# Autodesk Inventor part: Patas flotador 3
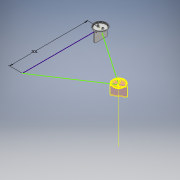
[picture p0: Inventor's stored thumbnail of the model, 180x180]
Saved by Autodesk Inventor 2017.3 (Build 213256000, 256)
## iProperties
Part Number: Patas flotador 3
Material: Genérico
Document SubType Name: Modeling
Designer: PABLO HERNANDEZ
Density: 1 g/cm^3
Appearance: Valor por defecto
Author: PABLO HERNANDEZ
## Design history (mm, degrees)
node "Geometría reparada1"
sketch "Boceto1"
  geometry: C1 r 16 at (0, 0); 1 further point
  constraints: 1 centre point, 1 coincident
  dimensions: "d0" = 32 diameter of C1
extrude "Extrusión1" new body sketch "Boceto1" distance "d1" = 1; taper "d2" = 0 deg; dims "d93" = 1, "d94" = 0
sketch "Boceto2"
  geometry: C1 r 16 at (0, 0); C2 r 15 at (0, 0); C3 r 14 at (0, 0); 1 further point
  constraints: 3 centre point, 1 coincident
  dimensions: "d3" = 1 radial gap between concentric circles of C1 C2; "d4" = 1 radial gap between concentric circles of C2 C3
extrude "Extrusión2" join sketch "Boceto2" distance "d5" = 3; taper "d6" = 0 deg
sketch "Boceto3"
  geometry: C1 r 15 at (0, 0); C2 r 14 at (0, 0); 1 further point
  constraints: 2 centre point, 1 coincident
  dimensions: "d7" = 1 radial gap between concentric circles of C1 C2; "d123" = 30 diameter of C1
extrude "Extrusión3" join sketch "Boceto3" distance "d8" = 2; taper "d9" = 0 deg
sketch "Boceto4"
  geometry: C1 r 16 at (0, 0); 1 further point
  constraints: 1 centre point, 1 coincident
extrude "Extrusión4" cut sketch "Boceto4" distance "d10" = 0.5; taper "d11" = 0 deg
sketch "Boceto7"
  geometry: L1 (1.5, -15.93)-(1.5, 15.93); L2 (-1.5, -15.93)-(-1.5, 15.93); A1 r 16 centre (0, 0) between (1.5, 15.93) and (-1.5, 15.93); A2 r 16 centre (0, 0) between (-1.5, -15.93) and (1.5, -15.93); 2 further points
  constraints: 4 end point, 4 point on circle, 2 centre point, 1 coincident
extrude "Extrusión7" join sketch "Boceto7" distance "d63" = 25; taper "d64" = 0 deg
fillet "Empalme1" dims "d71" = 2
fillet "Empalme2" dims "d95" = 3
fillet "Empalme3" dims "d96" = 0.5
sketch "Boceto12"
  geometry: C1 r 1.2 at (-6, 0); C2 r 1.2 at (6, 0); 2 further points
  constraints: 2 centre point, 1 coincident
  dimensions: "d104" = 6 distance of point (0, 0) point (-6, 0); "d114" = 2.4 diameter of C1; "d115" = 2.4 diameter of C2
extrude "Extrusión9" cut sketch "Boceto12" stored distance "d116" = 10; taper "d117" = 0 deg
sketch "Boceto13"
  geometry: C1 r 1.2 at (-6, 0) reference; C2 r 1.75 at (-6, 0); C3 r 1.2 at (6, 0) reference; C4 r 1.75 at (6, 0); 1 further point
  constraints: 2 centre point, 2 coincident
  dimensions: "d118" = 3.5 diameter of C2; "d119" = 3.5 diameter of C4
extrude "Extrusión10" join sketch "Boceto13" distance "d120" = 3; taper "d121" = 0 deg
fillet "Empalme4" dims "d122" = 1
sketch "Boceto14"
  geometry: 1 further point
sketch "Boceto15"
  geometry: C1 r 1.2 at (6, 0) reference; C2 r 2.5 at (6, 0); C3 r 1.2 at (-6, 0) reference; C4 r 2.5 at (-6, 0); 1 further point
  constraints: 2 centre point, 2 coincident
  dimensions: "d124" = 5 diameter of C2; "d125" = 5 diameter of C4
extrude "Extrusión11" cut sketch "Boceto15" distance "d126" = 10; taper "d127" = 0 deg
sketch "Boceto16"
  geometry: L1 (0, 0)-(0, -201); L2 (0, -201)-(149.324, -102.291); L3 (0, 0)-(149.324, -102.291); 1 further point
  constraints: 6 end point, 2 coincident, 1 vertical
  dimensions: "d130" = 201 distance of L1.start L1.end
node "Plano de trabajo1"
node "Plano de trabajo4"
node "Plano de trabajo5"
sketch "Boceto21"
  geometry: C1 r 2 at (0, 0); 1 further point
  constraints: 1 centre point
  dimensions: "d140" = 4 diameter of C1
sketch "Boceto23"
  geometry: 1 further point
sketch "Boceto24"
  geometry: C1 r 2 at (0, 0); 1 further point
  constraints: 1 centre point
node "Eje de trabajo1"
feature "Desplazar cuerpo2"
feature "Desplazar cuerpo3"
node "Sólido1"
sketch "Boceto22"
  geometry: L1 (0, 0)-(0, -201) reference; L2 (0, -201)-(149.324, -102.291) reference; L3 (149.324, -102.291)-(0, 0); L4 (217.029, -3.215)-(67.705, 99.076); 1 further point
  constraints: 4 end point, 1 parallel
  dimensions: "d157" = 120 distance between parallel lines of L4 L3; "d158" = 181 distance of L2.end L1.start (derived); "d159" = 181 distance of L4.start L4.end
feature "Compuesta1"
node "Sup2"
other parameters: "sa_0" = 4, "d153" = 149.324, "d154" = -102.291, "d155" = 0, "d156" = -9.86699
